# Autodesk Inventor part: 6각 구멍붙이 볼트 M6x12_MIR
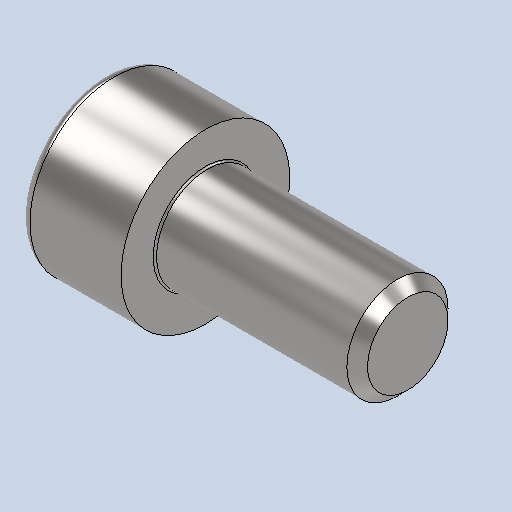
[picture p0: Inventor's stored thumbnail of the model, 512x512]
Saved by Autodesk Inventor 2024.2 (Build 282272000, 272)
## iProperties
Created: 2026-01
Part Number: 6각 구멍붙이 볼트 M6x12_MIR
Material: 강철, 연강
Description: 6각머리 태핑 나사
Document SubType Name: Modeling
Designer: home
Density: 7.85 g/cm^3
Appearance: 기본값
Author: jhkim
Sending System: Autodesk Inventor 2026
Preprocessor: ST-DEVELOPER v20.1
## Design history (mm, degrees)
derived "6각 구멍붙이 볼트 M6x12.ipt"
feature "솔리드1::6각 구멍붙이 볼트 M6x12.ipt" dims "d0" = 10
tag "피쳐 태그1"
node "솔리드1"
